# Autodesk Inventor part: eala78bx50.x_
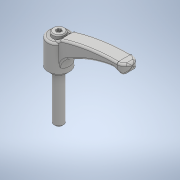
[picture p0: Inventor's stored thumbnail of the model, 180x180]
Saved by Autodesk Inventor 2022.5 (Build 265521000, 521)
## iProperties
Created: 2018-05
Part Number: eala78bx50.x_
Material: 一般
Document SubType Name: Modeling
Designer: imaocorp
Density: 1 g/cm^3
Appearance: 既定
Sending System: SOLIDWORKS 2016-2016286
MC: AMD64
MC_MODEL: AMD64 Family 21 Model 2 Stepping 0, AuthenticAMD
OS: Windows_NT
FRU: Parasolid Version 28.0, build 224,  7-29-2016
FORMAT: text
GUISE: transmit
KEY: eala78bx50
FILE: eala78bx50.x_t
DATE: Fri May 18 11:32:12 2018
Author: imaocorp
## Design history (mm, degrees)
feature "Base1"
node "ソリッド1"
